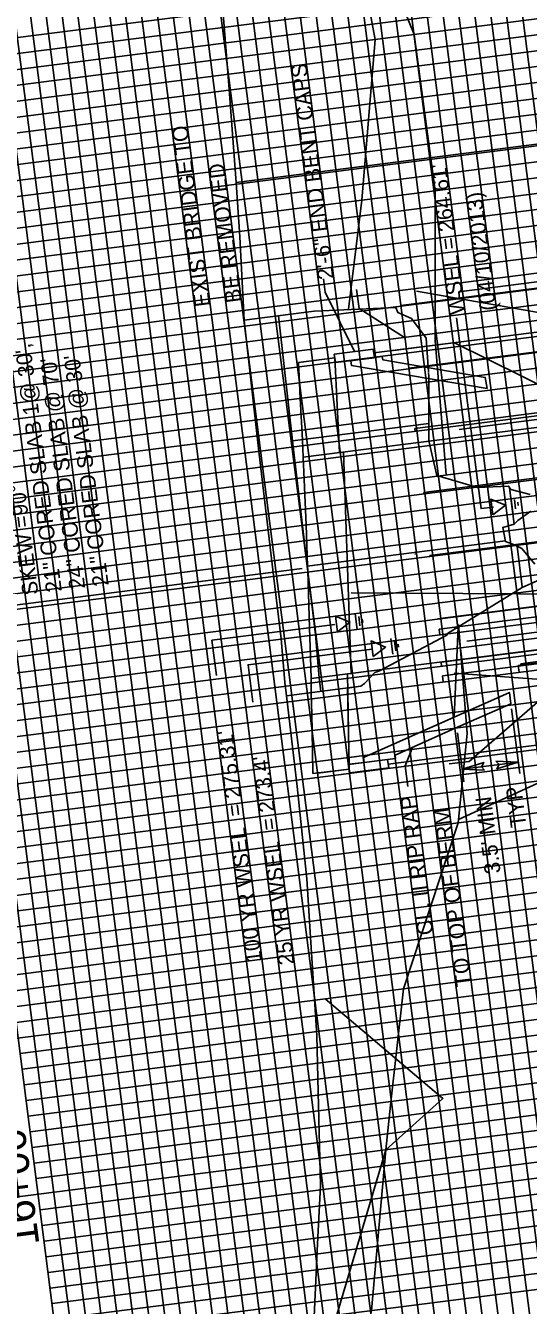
# Model space of a CAD drawing. Extents: x 2166991 to 2168413, y 842679 to 844296.
# Drawn here: x 2167677.7 to 2167837.4, y 843150.5 to 843556.7 of the extents above; entities that cross this region are included whole.
import ezdxf

# ---------------------------------------------------------------- set-up
doc = ezdxf.new("R2010")
doc.units = 0
for name, color, linetype in [('Exist Drainage Structure Bridge Floor', 7, 'Continuous'), ('Exist Horizontal Alignment', 7, 'Continuous'), ('Exist Hydrographic Natural Ground Left', 7, 'Continuous'), ('Exist Hydrographic Natural Ground Right', 7, 'Continuous'), ('Exist Vertical Profile Ground Line', 7, 'Continuous'), ('Old_Level_46', 7, 'Continuous'), ('Prop Drainage Structure Bridge', 7, 'Continuous'), ('Prop Erosion Rip Rap Class II', 7, 'Continuous'), ('Prop Hydrographic Scour Overtopping', 7, 'Continuous'), ('Prop Plan Preparation Drainage Notes Label', 7, 'Continuous'), ('Prop Plan Preparation Excavation Hatching', 7, 'Continuous'), ('Prop Plan Preparation Sheet Bridge Report Limited Study CELL', 7, 'Continuous'), ('Prop Plan Preparation Station Label', 7, 'Continuous'), ('Prop Plan Preparation Stream Water Surface', 7, 'Continuous'), ('Prop Plan Preparation Water Surface Symbol CELL', 7, 'Continuous'), ('Scratch_Level_2', 7, 'Continuous'), ('Scratch_Level_3', 7, 'Continuous'), ('Scratch_Level_4', 7, 'Continuous'), ('Scratch_Level_8', 7, 'Continuous')]:
    doc.layers.add(name, color=color, linetype=linetype)

msp = doc.modelspace()

# ---------------------------------------------------------------- linework, layer by layer
at = {"layer": 'Exist Drainage Structure Bridge Floor'}
for p, q in [((2167747.12, 843463.2), (2167769.41, 843466.04)), ((2167762.53, 843424.84), (2167805.8, 843430.37)), ((2167767.21, 843385.11), (2167830.11, 843393.15)), ((2167760.56, 843343.94), (2167784.24, 843346.96))]:
    msp.add_line(p, q, dxfattribs=at)
for points in [[(2167760.56, 843343.94), (2167760.1, 843348.27), (2167758.9, 843362.01), (2167756.48, 843382.13), (2167751.73, 843422.48), (2167747.12, 843463.2)], [(2167771.47, 843345.33), (2167771.01, 843349.66), (2167769.81, 843363.4), (2167767.4, 843383.52), (2167762.64, 843423.88), (2167758.03, 843464.59)]]:
    msp.add_lwpolyline(points, dxfattribs=at)
at = {"layer": 'Exist Horizontal Alignment'}
for points in [[(2167698.15, 843912.6), (2167700.9, 843897.02), (2167704.98, 843873.76), (2167712.78, 843830.82), (2167715.25, 843815.08), (2167719.44, 843788.58), (2167721.24, 843770.88), (2167724.14, 843742.72), (2167725.44, 843727.75), (2167727.98, 843698.45), (2167729.76, 843678.17), (2167732.36, 843648.31), (2167734.01, 843631.06), (2167736.91, 843601.24), (2167740.82, 843556.48), (2167742.38, 843536.39), (2167744.64, 843506.82), (2167745.73, 843489.59), (2167747.12, 843463.2)], [(2167751.39, 842824.91), (2167752.39, 842844.74), (2167753.95, 842874.72), (2167755.15, 842897.27), (2167757.06, 842927.31), (2167757.92, 842945.41), (2167760.09, 842975.47), (2167761.25, 842993.97), (2167762.76, 843023.98), (2167763.76, 843044.55), (2167765.23, 843074.51), (2167766.29, 843095.78), (2167768.15, 843125.8), (2167769.02, 843139.96), (2167770.48, 843169.95), (2167771.39, 843188.46), (2167770.67, 843218.15), (2167770.25, 843236.07), (2167768.33, 843265.68), (2167767.02, 843285.86), (2167763.97, 843315.19), (2167760.56, 843343.94)]]:
    msp.add_lwpolyline(points, dxfattribs=at)
at = {"layer": 'Exist Hydrographic Natural Ground Left'}
for points in [[(2167811.3, 843414.12), (2167807.83, 843456.76), (2167807.84, 843504.28), (2167801.18, 843553.83), (2167790.23, 843580.86), (2167790.98, 843602.94), (2167784.08, 843652.46), (2167781.01, 843702.48), (2167748.47, 843748.73), (2167729.16, 843847.07), (2167716.86, 843895.91), (2167712.99, 843945.82), (2167712.65, 843970.98), (2167709.18, 843995.74)], [(2167757.79, 842963.56), (2167770.55, 842995.45), (2167773.98, 843046.3), (2167776.61, 843068.3), (2167777.35, 843097.13), (2167787.62, 843148.85), (2167792.18, 843199.84), (2167793.61, 843214.01), (2167797.76, 843250.96), (2167815.06, 843303.58), (2167817.99, 843332.01), (2167815.17, 843366.59)]]:
    msp.add_lwpolyline(points, dxfattribs=at)
at = {"layer": 'Exist Hydrographic Natural Ground Right'}
for points in [[(2167780.31, 843466.62), (2167784.52, 843501.3), (2167788.71, 843552.24), (2167783.57, 843580.01), (2167779.35, 843601.45), (2167769.15, 843650.56), (2167754.8, 843699.13), (2167753.25, 843749.34), (2167741.46, 843798.24), (2167722.31, 843846.2), (2167712.49, 843895.35), (2167692.49, 843943.2), (2167687.3, 843967.74), (2167682.51, 843992.33)], [(2167764.31, 843094.3), (2167776.57, 843147.44), (2167792.18, 843199.84), (2167810.26, 843216.13), (2167772.9, 843247.78)]]:
    msp.add_lwpolyline(points, dxfattribs=at)
at = {"layer": 'Exist Vertical Profile Ground Line'}
msp.add_line((2167795.37, 843467.16), (2167769.41, 843466.04), dxfattribs=at)
for points in [[(2167805.68, 843446.76), (2167804.98, 843457.45), (2167800.25, 843463.71), (2167795.92, 843465.61), (2167795.37, 843467.16)], [(2167837.93, 843407.87), (2167831.79, 843409.39), (2167831.14, 843410.52), (2167821.21, 843410.07), (2167808.38, 843413.88), (2167805.82, 843424.85), (2167805.79, 843436.55), (2167805.78, 843445.31), (2167805.69, 843446.57)], [(2167839.45, 843385.69), (2167835.28, 843390.74), (2167832.96, 843391.91), (2167830.17, 843392.87), (2167829.29, 843397.37), (2167832.89, 843398.38), (2167834.04, 843399.62), (2167838.15, 843402.55)], [(2167784.24, 843346.96), (2167785.37, 843347.8), (2167788.65, 843351.29), (2167790.08, 843351.91), (2167811.52, 843363.23), (2167811.76, 843363.73), (2167835.45, 843378.32), (2167840.17, 843380.47)]]:
    msp.add_lwpolyline(points, dxfattribs=at)
at = {"layer": 'Old_Level_46'}
for points in [[(2167798.06, 843457.66), (2167783.65, 843466.84), (2167782.87, 843472.96)], [(2167814.63, 843463.88), (2167822.41, 843403.37), (2167826.31, 843403.86)], [(2167775.92, 843366.58), (2167736.94, 843361.6), (2167738.37, 843350.34)], [(2167787.78, 843358.8), (2167748.42, 843353.78), (2167749.94, 843341.89)]]:
    msp.add_lwpolyline(points, dxfattribs=at)
at = {"layer": 'Prop Drainage Structure Bridge'}
for p, q in [((2167788.33, 843452.77), (2167829.5, 843458.03)), ((2167794.54, 843453.55), (2167848.25, 843460.41)), ((2167775.78, 843452.41), (2167788.18, 843454)), ((2167788.17, 843454), (2167788.52, 843451.28)), ((2167764.37, 843449.7), (2167775.94, 843451.17)), ((2167766.02, 843449.91), (2167775.94, 843451.17)), ((2167776.13, 843449.69), (2167788.53, 843451.27)), ((2167765.91, 843419.65), (2167960.44, 843444.5)), ((2167768.38, 843349.4), (2167969.63, 843375.1)), ((2167821.41, 843325.93), (2167864.73, 843331.46)), ((2167780.32, 843322.19), (2167792.72, 843323.77)), ((2167793.05, 843321.04), (2167792.71, 843323.76)), ((2167792.9, 843322.27), (2167834.07, 843327.53)), ((2167768.96, 843319.23), (2167780.51, 843320.7)), ((2167770.59, 843319.44), (2167780.51, 843320.7)), ((2167780.67, 843319.46), (2167793.07, 843321.05))]:
    msp.add_line(p, q, dxfattribs=at)
for points in [[(2167768.96, 843319.23), (2167768.73, 843332.94), (2167768.63, 843337.97), (2167768.48, 843344.95), (2167768.38, 843349.4), (2167768.21, 843356.31), (2167767.95, 843365.56), (2167767.37, 843383.75), (2167767.32, 843385.13), (2167766.83, 843398.23), (2167765.91, 843419.65), (2167765.64, 843425.24), (2167764.98, 843438.32), (2167764.72, 843443.32), (2167764.37, 843449.7)], [(2167780.51, 843320.7), (2167779.93, 843350.87), (2167781.17, 843351.03), (2167778.7, 843421.28), (2167777.46, 843421.13), (2167775.94, 843451.17)]]:
    msp.add_lwpolyline(points, dxfattribs=at)
at = {"layer": 'Prop Erosion Rip Rap Class II'}
for points in [[(2167781.08, 843450.32), (2167781.28, 843448.75), (2167824.28, 843441.49), (2167823.72, 843445.01), (2167791.15, 843450.59), (2167790.99, 843451.61), (2167788.51, 843451.29)], [(2167785.27, 843322.82), (2167785.06, 843324.39), (2167831.4, 843345.02), (2167831.8, 843341.39), (2167814.14, 843333.63), (2167795.08, 843325.09), (2167795.19, 843324.06), (2167792.71, 843323.75)]]:
    msp.add_lwpolyline(points, close=True, dxfattribs=at)
at = {"layer": 'Prop Hydrographic Scour Overtopping'}
for p, q in [((2167960.44, 843444.56), (2167801.84, 843472.35)), ((2167969.56, 843375.09), (2167815.18, 843304.73)), ((2167814.98, 843365.72), (2167814.45, 843369.88))]:
    msp.add_line(p, q, dxfattribs=at)
at = {"layer": 'Prop Plan Preparation Drainage Notes Label'}
for p, q in [((2167801.93, 843388.97), (2167801.38, 843388.9)), ((2167765.56, 843384.32), (2167668.02, 843371.86)), ((2167832.06, 843339.76), (2167834.67, 843319.3)), ((2167814.9, 843332.2), (2167816.89, 843316.6)), ((2167816.37, 843320.64), (2167834.21, 843322.92)), ((2167823.97, 843296.65), (2167823.97, 843296.58))]:
    msp.add_line(p, q, dxfattribs=at)
for points in [[(2167772.38, 843476.34), (2167772.93, 843472.04), (2167782.2, 843453.23)], [(2167895.15, 843315.83), (2167893.14, 843331.53), (2167887.44, 843375.99), (2167781.12, 843376.66)], [(2167854.04, 843318.38), (2167850.29, 843348.53), (2167813.82, 843351.12)], [(2167799.13, 843315.18), (2167798.3, 843321.71), (2167800.64, 843327.58)]]:
    msp.add_lwpolyline(points, dxfattribs=at)
for points in [[(2167823.5, 843320.33), (2167816.37, 843320.64), (2167823.23, 843322.78), (2167822.49, 843321.42)], [(2167827.08, 843323.23), (2167834.21, 843322.92), (2167827.35, 843320.79), (2167828.09, 843322.14)]]:
    msp.add_lwpolyline(points, close=True, dxfattribs=at)
at = {"layer": 'Prop Plan Preparation Excavation Hatching'}
for p, q in [((2167776.13, 843449.7), (2167775.78, 843452.43)), ((2167780.32, 843322.17), (2167780.67, 843319.45))]:
    msp.add_line(p, q, dxfattribs=at)
msp.add_lwpolyline([(2167780.51, 843322.21), (2167780.02, 843346.42), (2167784.24, 843346.96), (2167785.37, 843347.8), (2167788.65, 843351.29), (2167790.08, 843351.91), (2167811.52, 843363.23), (2167811.76, 843363.73), (2167815.13, 843365.81), (2167813.8, 843337.17), (2167785.06, 843324.39), (2167785.27, 843322.82), (2167781.42, 843322.33)], close=True, dxfattribs=at)
at = {"layer": 'Prop Plan Preparation Sheet Bridge Report Limited Study CELL'}
for p, q in [((2167933.95, 842789.5), (2167775.57, 844029.42)), ((2167884.35, 842783.16), (2167725.98, 844023.09)), ((2167834.76, 842776.83), (2167676.38, 844016.75)), ((2167785.16, 842770.49), (2167626.78, 844010.42)), ((2167735.56, 842764.16), (2167577.19, 844004.08)), ((2167910.94, 842811.76), (2167758.9, 844002.09)), ((2167915.9, 842812.39), (2167763.86, 844002.72)), ((2167920.86, 842813.03), (2167768.82, 844003.36)), ((2167925.82, 842813.66), (2167773.78, 844003.99)), ((2167886.15, 842808.59), (2167734.11, 843998.92)), ((2167891.11, 842809.23), (2167739.06, 843999.56)), ((2167896.07, 842809.86), (2167744.02, 844000.19)), ((2167901.03, 842810.49), (2167748.98, 844000.82)), ((2167905.98, 842811.13), (2167753.94, 844001.46)), ((2167851.43, 842804.16), (2167699.39, 843994.49)), ((2167856.39, 842804.79), (2167704.35, 843995.12)), ((2167861.35, 842805.43), (2167709.31, 843995.76)), ((2167866.31, 842806.06), (2167714.27, 843996.39)), ((2167871.27, 842806.69), (2167719.23, 843997.02)), ((2167876.23, 842807.33), (2167724.19, 843997.66)), ((2167816.71, 842799.72), (2167664.67, 843990.05)), ((2167821.67, 842800.36), (2167669.63, 843990.69)), ((2167826.63, 842800.99), (2167674.59, 843991.32)), ((2167836.55, 842802.26), (2167684.51, 843992.59)), ((2167841.51, 842802.89), (2167689.47, 843993.22)), ((2167846.47, 842803.53), (2167694.43, 843993.85)), ((2167786.95, 842795.92), (2167634.91, 843986.25)), ((2167791.91, 842796.56), (2167639.87, 843986.89)), ((2167796.87, 842797.19), (2167644.83, 843987.52)), ((2167801.83, 842797.82), (2167649.79, 843988.15)), ((2167806.79, 842798.46), (2167654.75, 843988.79)), ((2167811.75, 842799.09), (2167659.71, 843989.42)), ((2167752.23, 842791.49), (2167600.19, 843981.82)), ((2167757.19, 842792.12), (2167605.15, 843982.45)), ((2167762.15, 842792.76), (2167610.11, 843983.09)), ((2167767.11, 842793.39), (2167615.07, 843983.72)), ((2167772.07, 842794.02), (2167620.03, 843984.35)), ((2167777.03, 842794.66), (2167624.99, 843984.99)), ((2167737.35, 842789.59), (2167585.31, 843979.92)), ((2167742.31, 842790.22), (2167590.27, 843980.55)), ((2167747.27, 842790.86), (2167595.23, 843981.18)), ((2168131.44, 843611.14), (2167635.47, 843547.79)), ((2168132.07, 843606.18), (2167636.1, 843542.83)), ((2168132.71, 843601.22), (2167636.74, 843537.87)), ((2168133.34, 843596.26), (2167612.57, 843529.74)), ((2168133.97, 843591.3), (2167638, 843527.95)), ((2168134.61, 843586.34), (2167638.64, 843522.99)), ((2168135.24, 843581.38), (2167639.27, 843518.03)), ((2168135.87, 843576.42), (2167639.9, 843513.07)), ((2168136.51, 843571.46), (2167640.54, 843508.11)), ((2168137.14, 843566.5), (2167641.17, 843503.15)), ((2168137.77, 843561.54), (2167641.8, 843498.19)), ((2168138.41, 843556.58), (2167642.44, 843493.23)), ((2168139.04, 843551.62), (2167643.07, 843488.27)), ((2168139.68, 843546.66), (2167618.91, 843480.15)), ((2168140.31, 843541.7), (2167644.34, 843478.35)), ((2168140.94, 843536.74), (2167644.97, 843473.39)), ((2168141.58, 843531.78), (2167645.61, 843468.43)), ((2168142.21, 843526.83), (2167646.24, 843463.47)), ((2168142.84, 843521.87), (2167646.87, 843458.52)), ((2168143.48, 843516.91), (2167647.51, 843453.56)), ((2168144.11, 843511.95), (2167648.14, 843448.6)), ((2168144.74, 843506.99), (2167648.77, 843443.64)), ((2168145.38, 843502.03), (2167649.41, 843438.68)), ((2168146.01, 843497.07), (2167625.24, 843430.55)), ((2168146.64, 843492.11), (2167650.67, 843428.76)), ((2168147.28, 843487.15), (2167651.31, 843423.8)), ((2168147.91, 843482.19), (2167651.94, 843418.84)), ((2168148.54, 843477.23), (2167652.57, 843413.88)), ((2168149.18, 843472.27), (2167653.21, 843408.92)), ((2168149.81, 843467.31), (2167653.84, 843403.96)), ((2168150.44, 843462.35), (2167654.47, 843399)), ((2168151.08, 843457.39), (2167655.11, 843394.04)), ((2168151.71, 843452.43), (2167655.74, 843389.08)), ((2168152.35, 843447.47), (2167631.58, 843380.95)), ((2168152.98, 843442.51), (2167657.01, 843379.16)), ((2168153.61, 843437.55), (2167657.64, 843374.2)), ((2168154.25, 843432.59), (2167658.28, 843369.24)), ((2168154.88, 843427.63), (2167658.91, 843364.28)), ((2168155.51, 843422.67), (2167659.54, 843359.32)), ((2168156.15, 843417.71), (2167660.18, 843354.36)), ((2168156.78, 843412.75), (2167660.81, 843349.4)), ((2168157.41, 843407.79), (2167661.44, 843344.44)), ((2168158.05, 843402.83), (2167662.08, 843339.48)), ((2168158.68, 843397.87), (2167637.91, 843331.35)), ((2168159.31, 843392.91), (2167663.34, 843329.56)), ((2168159.95, 843387.95), (2167663.98, 843324.6)), ((2168160.58, 843382.99), (2167664.61, 843319.64)), ((2168161.21, 843378.03), (2167665.24, 843314.68)), ((2168161.85, 843373.07), (2167665.88, 843309.72)), ((2168162.48, 843368.11), (2167666.51, 843304.76)), ((2168163.11, 843363.15), (2167667.14, 843299.8)), ((2168163.75, 843358.2), (2167667.78, 843294.84)), ((2168164.38, 843353.24), (2167668.41, 843289.89)), ((2168165.02, 843348.28), (2167644.25, 843281.76)), ((2168165.65, 843343.32), (2167669.68, 843279.97)), ((2168166.28, 843338.36), (2167670.31, 843275.01)), ((2168166.92, 843333.4), (2167670.95, 843270.05)), ((2168167.55, 843328.44), (2167671.58, 843265.09)), ((2168168.18, 843323.48), (2167672.21, 843260.13)), ((2168168.82, 843318.52), (2167672.85, 843255.17)), ((2168169.45, 843313.56), (2167673.48, 843250.21)), ((2168170.08, 843308.6), (2167674.11, 843245.25)), ((2168170.72, 843303.64), (2167674.75, 843240.29)), ((2168171.35, 843298.68), (2167650.58, 843232.16)), ((2168171.98, 843293.72), (2167676.01, 843230.37)), ((2168172.62, 843288.76), (2167676.65, 843225.41)), ((2168173.25, 843283.8), (2167677.28, 843220.45)), ((2168173.88, 843278.84), (2167677.91, 843215.49)), ((2168174.52, 843273.88), (2167678.55, 843210.53)), ((2168175.15, 843268.92), (2167679.18, 843205.57)), ((2168175.78, 843263.96), (2167679.81, 843200.61)), ((2168176.42, 843259), (2167680.45, 843195.65)), ((2168177.05, 843254.04), (2167681.08, 843190.69)), ((2168177.69, 843249.08), (2167656.92, 843182.56)), ((2168178.32, 843244.12), (2167682.35, 843180.77)), ((2168178.95, 843239.16), (2167682.98, 843175.81)), ((2168179.59, 843234.2), (2167683.62, 843170.85)), ((2168180.22, 843229.24), (2167684.25, 843165.89)), ((2168180.85, 843224.28), (2167684.88, 843160.93)), ((2168181.49, 843219.32), (2167685.52, 843155.97)), ((2168182.12, 843214.36), (2167686.15, 843151.01)), ((2168182.75, 843209.4), (2167686.78, 843146.05)), ((2168183.39, 843204.44), (2167687.42, 843141.09)), ((2168184.02, 843199.48), (2167663.25, 843132.97))]:
    msp.add_line(p, q, dxfattribs=at)
at = {"layer": 'Prop Plan Preparation Stream Water Surface'}
for p, q in [((2167832.93, 843398.43), (2167831.46, 843409.95)), ((2167835.48, 843378.51), (2167833.82, 843391.48))]:
    msp.add_line(p, q, dxfattribs=at)
at = {"layer": 'Prop Plan Preparation Water Surface Symbol CELL'}
for p, q in [((2167832.46, 843402.13), (2167831.83, 843407.09)), ((2167833.33, 843403.25), (2167832.95, 843406.22)), ((2167834.19, 843404.36), (2167834.07, 843405.36)), ((2167783.07, 843365.02), (2167782.43, 843369.98)), ((2167783.93, 843366.14), (2167783.55, 843369.11)), ((2167784.8, 843367.25), (2167784.67, 843368.25)), ((2167794.41, 843357.13), (2167793.77, 843362.09)), ((2167795.27, 843358.25), (2167794.89, 843361.22)), ((2167796.14, 843359.36), (2167796.01, 843360.36))]:
    msp.add_line(p, q, dxfattribs=at)
for points in [[(2167826.14, 843401.4), (2167825.51, 843406.36), (2167830.13, 843404.43)], [(2167776.75, 843364.29), (2167776.11, 843369.25), (2167780.73, 843367.32)], [(2167788.09, 843356.4), (2167787.45, 843361.35), (2167792.07, 843359.42)]]:
    msp.add_lwpolyline(points, close=True, dxfattribs=at)
at = {"layer": 'Scratch_Level_2'}
for p, q in [((2168101.65, 843552.42), (2167744.64, 843506.82)), ((2167742.39, 843536.24), (2167742.38, 843536.39)), ((2167744.71, 843506.3), (2167744.64, 843506.82))]:
    msp.add_line(p, q, dxfattribs=at)
at = {"layer": 'Scratch_Level_3'}
for p, q in [((2167815.39, 843428.51), (2168411.81, 843504.69)), ((2167858.33, 843434), (2167813.96, 843456.03)), ((2167817.84, 843361.31), (2168278.64, 843420.17)), ((2167870.26, 843368), (2167818.59, 843323.14)), ((2167818.59, 843323.14), (2167812.28, 843322.33))]:
    msp.add_line(p, q, dxfattribs=at)
at = {"layer": 'Scratch_Level_4'}
for p, q in [((2168088.64, 843507.14), (2167815.29, 843472.22)), ((2167815.58, 843469.98), (2167815.29, 843472.22)), ((2168083.95, 843385.46), (2167834.18, 843353.55)), ((2168082.98, 843385.82), (2167834.96, 843354.14)), ((2167834.45, 843351.42), (2167834.18, 843353.55)), ((2167835.02, 843353.66), (2167834.96, 843354.14))]:
    msp.add_line(p, q, dxfattribs=at)
at = {"layer": 'Scratch_Level_8'}
for p, q in [((2168091.54, 843505.51), (2167796.91, 843467.87)), ((2168090.16, 843485.03), (2167799.4, 843447.89)), ((2167796.94, 843467.6), (2167796.91, 843467.87)), ((2168089.2, 843465.59), (2167801.33, 843428.82)), ((2167799.41, 843447.76), (2167799.4, 843447.89)), ((2168087.87, 843444.75), (2167804.17, 843408.52)), ((2167801.45, 843427.85), (2167801.33, 843428.82)), ((2168086.81, 843424.32), (2167806.08, 843388.46)), ((2167804.23, 843408.05), (2167804.17, 843408.52)), ((2168086.26, 843403.82), (2167808.5, 843368.34)), ((2168086.42, 843400.54), (2167809.11, 843365.12)), ((2168085.19, 843389.79), (2167809.7, 843354.6)), ((2167806.12, 843388.13), (2167806.08, 843388.46)), ((2168085.19, 843385.4), (2167810.15, 843350.27)), ((2167808.51, 843368.27), (2167808.5, 843368.34)), ((2167809.34, 843363.33), (2167809.11, 843365.12)), ((2167809.86, 843353.32), (2167809.7, 843354.6)), ((2167810.4, 843348.35), (2167810.15, 843350.27))]:
    msp.add_line(p, q, dxfattribs=at)

# ---------------------------------------------------------------- texts
at = {"layer": 'Old_Level_46'}
for s, p in [('EXIST BRIDGE TO', (2167736.43, 843467.74)), ('BE REMOVED', (2167746.35, 843469.01)), ("WSEL = 264.61'", (2167817.32, 843465.21)), ('(04/10/2013)', (2167827.24, 843466.48)), ("100 YR WSEL  = 275.31'", (2167752.81, 843259.57)), ("25 YR WSEL  = 273.4'", (2167763.11, 843258.81))]:
    msp.add_text(s, height=5, rotation=97.279, dxfattribs=at).set_placement(p)
at = {"layer": 'Prop Plan Preparation Drainage Notes Label'}
for s, p in [('2\'-6" END BENT CAPS', (2167775.63, 843476.4)), ('21" CORED SLAB 1@ 30\',', (2167689.28, 843377.14)), ('24" CORED SLAB @ 70\'', (2167696.72, 843378.09)), ('21" CORED SLAB @ 30\'', (2167704.16, 843379.04)), ('SKEW =90%%d', (2167681.84, 843376.19)), ('CL. II RIP RAP', (2167807.28, 843268.29)), ("3.5' MIN", (2167828.62, 843287.77)), ('TYP', (2167836.81, 843302.55)), ('TO TOP OF BERM', (2167819.45, 843251.91))]:
    msp.add_text(s, height=5, rotation=97.279, dxfattribs=at).set_placement(p)
at = {"layer": 'Prop Plan Preparation Station Label'}
msp.add_text('16+00', height=10, rotation=97.279, dxfattribs=at).set_placement((2167682.16, 843169.8))

doc.saveas('drawing.dxf')
